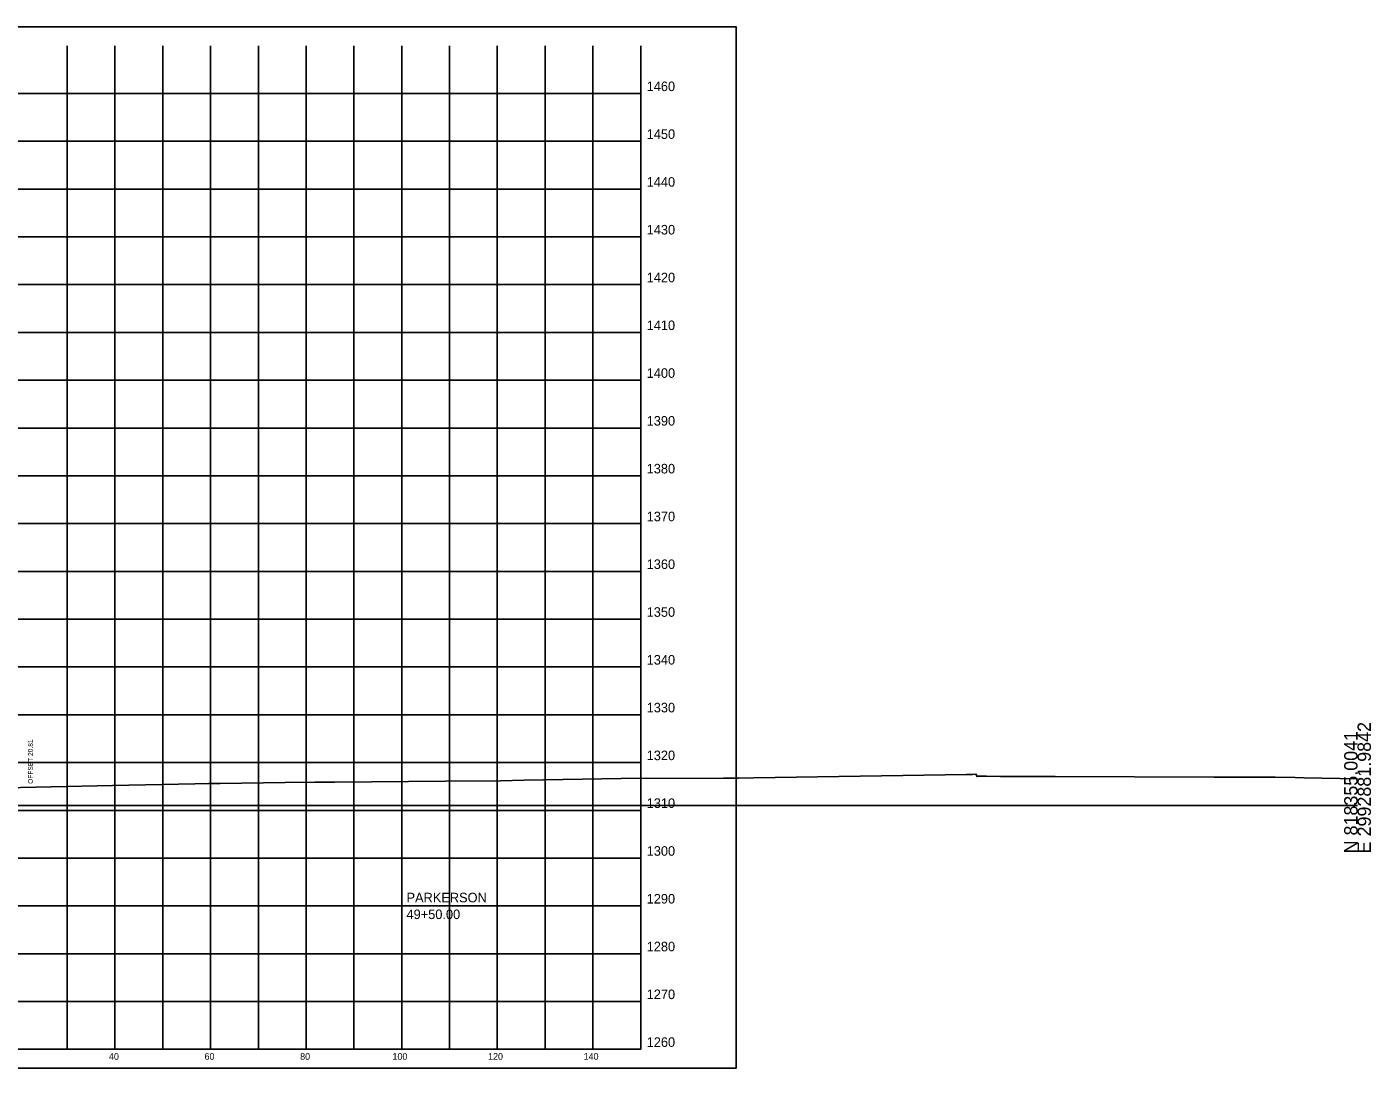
# Model space of a CAD drawing. Extents: x -26 to 603, y -60 to 663.
# Drawn here: x 321.6 to 602.8, y 445.1 to 662.9 of the extents above; entities that cross this region are included whole.
import ezdxf

# ---------------------------------------------------------------- set-up
doc = ezdxf.new("R2010")
doc.units = 0
for name, color, linetype in [('DESIGN - SHEET - Corner Text', 7, 'Continuous'), ('DESIGN - SHEET - Light Grid', 7, 'Continuous'), ('DESIGN - SHEET - Linework', 7, 'Continuous'), ('DESIGN - SHEET - Plot Shape', 7, 'Continuous'), ('DESIGN - TYPICAL - Slope Tie Text', 7, 'Continuous'), ('DESIGN - TYPICAL - Warning Text', 7, 'Continuous'), ('SURVEY - GROUND - Top of Ground', 7, 'Continuous')]:
    doc.layers.add(name, color=color, linetype=linetype)

msp = doc.modelspace()

# ---------------------------------------------------------------- linework, layer by layer
at = {"layer": 'DESIGN - SHEET - Light Grid'}
msp.add_line((300, 500), (600, 500), dxfattribs=at)
at = {"layer": 'DESIGN - SHEET - Linework'}
for p, q in [((330, 449), (330, 659)), ((340, 449), (340, 659)), ((350, 449), (350, 659)), ((360, 449), (360, 659)), ((370, 449), (370, 659)), ((380, 449), (380, 659)), ((390, 449), (390, 659)), ((400, 449), (400, 659)), ((410, 449), (410, 659)), ((420, 449), (420, 659)), ((430, 449), (430, 659)), ((440, 449), (440, 659)), ((150, 649), (450, 649)), ((150, 639), (450, 639)), ((150, 629), (450, 629)), ((150, 619), (450, 619)), ((150, 609), (450, 609)), ((150, 599), (450, 599)), ((150, 589), (450, 589)), ((150, 579), (450, 579)), ((150, 569), (450, 569)), ((150, 559), (450, 559)), ((150, 549), (450, 549)), ((150, 539), (450, 539)), ((150, 529), (450, 529)), ((150, 519), (450, 519)), ((150, 509), (450, 509)), ((150, 499), (450, 499)), ((150, 489), (450, 489)), ((150, 479), (450, 479)), ((150, 469), (450, 469)), ((150, 459), (450, 459))]:
    msp.add_line(p, q, dxfattribs=at)
msp.add_lwpolyline([(150, 659), (150, 449), (450, 449), (450, 659)], dxfattribs=at)
at = {"layer": 'DESIGN - SHEET - Plot Shape'}
msp.add_lwpolyline([(130, 662.94), (470, 662.94), (470, 445.06), (130, 445.06)], close=True, dxfattribs=at)
at = {"layer": 'SURVEY - GROUND - Top of Ground'}
msp.add_lwpolyline([(317.01, 503.73), (339.49, 504.19), (356.71, 504.55), (359.63, 504.6), (361.98, 504.63), (375.59, 504.82), (381.83, 504.91), (385.92, 504.91), (409.13, 505.07), (420.66, 505.15), (425.6, 505.28), (445.9, 505.66), (467.31, 505.75), (470.46, 505.74), (473.69, 505.77), (518.2, 506.52), (519.43, 506.51), (520.14, 506.59), (520.4, 506.07), (520.46, 506.16), (521.8, 506.15), (522.35, 506.14), (525.26, 506.1), (530.21, 506.08), (533.51, 506.08), (536.71, 506.07), (569.93, 505.94), (570.83, 505.95), (574.74, 505.94), (582.78, 505.93), (586.97, 505.87), (588.83, 505.82), (600, 505.58)], dxfattribs=at)

# ---------------------------------------------------------------- texts
at = {"layer": 'DESIGN - SHEET - Corner Text'}
for s, height, p in [('1460', 2, (451.25, 649.5)), ('1450', 2, (451.25, 639.5)), ('1440', 2, (451.25, 629.5)), ('1430', 2, (451.25, 619.5)), ('1420', 2, (451.25, 609.5)), ('1410', 2, (451.25, 599.5)), ('1400', 2, (451.25, 589.5)), ('1390', 2, (451.25, 579.5)), ('1380', 2, (451.25, 569.5)), ('1370', 2, (451.25, 559.5)), ('1360', 2, (451.25, 549.5)), ('1350', 2, (451.25, 539.5)), ('1340', 2, (451.25, 529.5)), ('1330', 2, (451.25, 519.5)), ('1320', 2, (451.25, 509.5)), ('1310', 2, (451.25, 499.5)), ('1300', 2, (451.25, 489.5)), ('1290', 2, (451.25, 479.5)), ('1280', 2, (451.25, 469.5)), ('1270', 2, (451.25, 459.5)), ('1260', 2, (451.25, 449.5)), ('40', 1.4, (338.74, 446.8)), ('60', 1.4, (358.74, 446.8)), ('80', 1.4, (378.74, 446.8)), ('100', 1.4, (398.06, 446.8)), ('120', 1.4, (418.06, 446.8)), ('140', 1.4, (438.06, 446.8))]:
    msp.add_text(s, height=height, dxfattribs=at).set_placement(p)
at = {"layer": 'DESIGN - SHEET - Light Grid'}
for s, p in [('N 818355.0041', (600, 490)), ('E 2992881.9842', (602.8, 490))]:
    msp.add_text(s, height=2.8, rotation=90, dxfattribs=at).set_placement(p)
at = {"layer": 'DESIGN - TYPICAL - Slope Tie Text'}
msp.add_text('OFFSET 20.81', height=1, rotation=90, dxfattribs=at).set_placement((322.81, 504.55))
at = {"layer": 'DESIGN - TYPICAL - Warning Text'}
for s, p in [('PARKERSON', (401, 479.75)), ('49+50.00', (401, 476.25))]:
    msp.add_text(s, height=2, dxfattribs=at).set_placement(p)

doc.saveas('drawing.dxf')
